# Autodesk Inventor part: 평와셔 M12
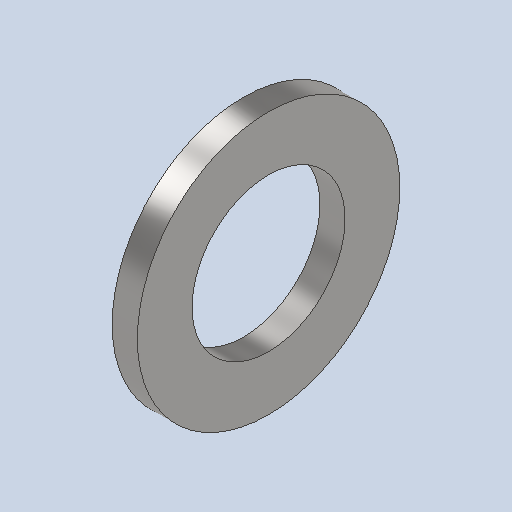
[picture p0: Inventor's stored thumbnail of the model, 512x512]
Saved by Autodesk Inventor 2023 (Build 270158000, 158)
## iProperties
Created: 2024-07
Part Number: 평와셔 M12
Material: 강철, 연강
Description: 평면 와셔
Document SubType Name: Modeling
Designer: home
Density: 7.85 g/cm^3
Appearance: 기본값
Author: jhkim
Sending System: Autodesk Inventor 2025
Preprocessor: ST-DEVELOPER v20
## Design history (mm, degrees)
feature "Solid1"
node "솔리드1"
